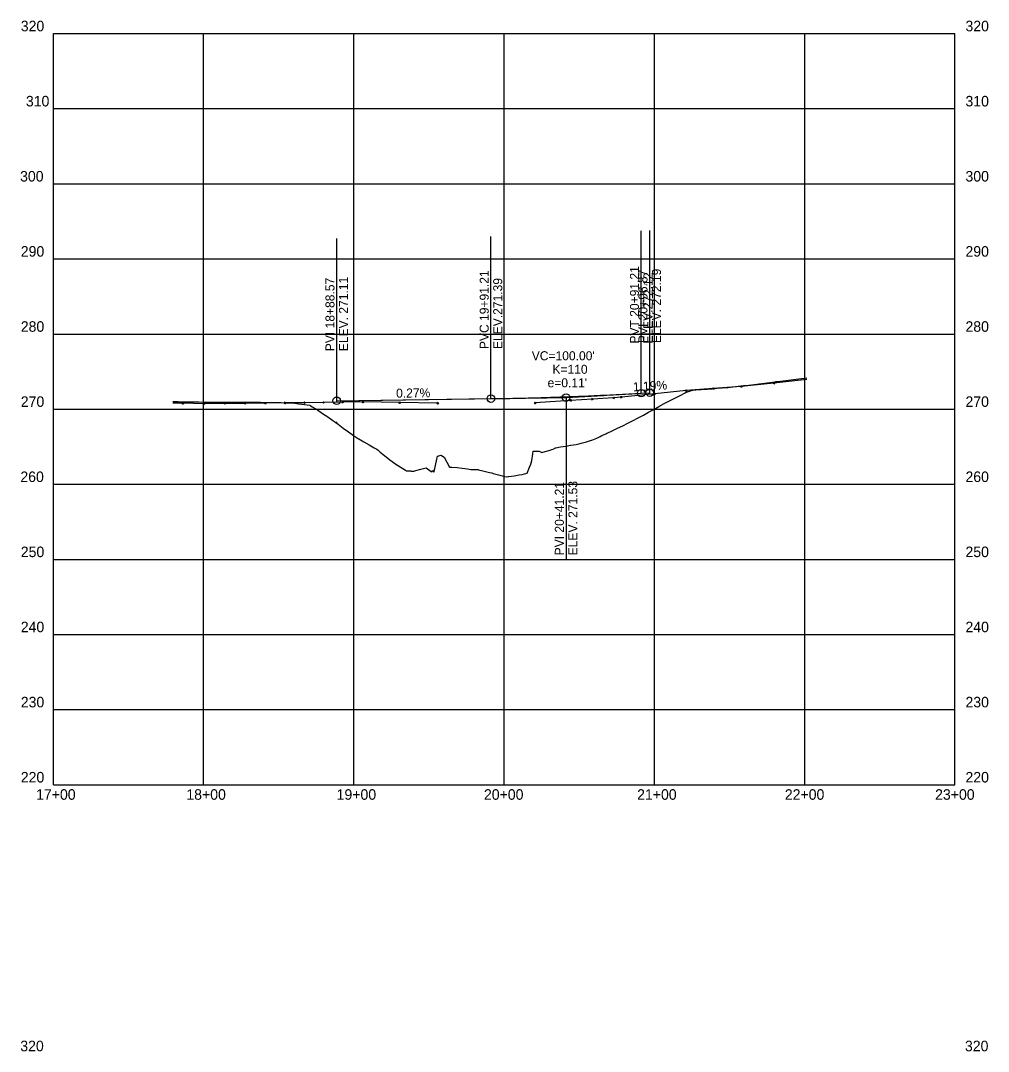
# Model space of a CAD drawing. Extents: x 1661035 to 1663788, y 668049 to 670894.
# Drawn here: x 1663144 to 1663788, y 670208 to 670894 of the extents above; entities that cross this region are included whole.
import ezdxf

# ---------------------------------------------------------------- set-up
doc = ezdxf.new("R2010")
doc.units = 0
for name, color, linetype in [('Default', 7, 'Continuous'), ('R_Axis', 7, 'Continuous'), ('R_Axis Annot', 7, 'Continuous'), ('R_Exist Surface', 7, 'Continuous'), ('R_Grid', 7, 'Continuous'), ('R_Point Sym', 7, 'Continuous'), ('R_Vert Alg', 7, 'Continuous'), ('R_Vert Alg Annot', 7, 'Continuous')]:
    doc.layers.add(name, color=color, linetype=linetype)

msp = doc.modelspace()

# ---------------------------------------------------------------- linework, layer by layer
at = {"layer": 'Default'}
for p, q in [((1663562.59, 670645.43), (1663562.59, 670646.43)), ((1663354.29, 670640.13), (1663354.29, 670641.13)), ((1663354.29, 670626.19), (1663354.29, 670627.19))]:
    msp.add_line(p, q, dxfattribs=at)
for points in [[(1663667.15, 670655.23), (1663645.28, 670652.95), (1663623.55, 670650.66), (1663604.92, 670649.27), (1663586.87, 670647.88), (1663565.94, 670645.75), (1663543.74, 670643.62), (1663538.59, 670643.09), (1663524.44, 670642.23), (1663509.96, 670641.37), (1663486.35, 670639.69)], [(1663421.48, 670639.45), (1663396.14, 670639.9), (1663371.72, 670640.36), (1663358.26, 670640.18), (1663345.5, 670640.01), (1663332.86, 670639.83), (1663319.87, 670639.66), (1663306.73, 670639.52), (1663293.35, 670639.39), (1663279.78, 670639.26), (1663266.06, 670639.13), (1663251.98, 670639.46), (1663245.29, 670639.62)]]:
    msp.add_lwpolyline(points, dxfattribs=at)
at = {"layer": 'R_Axis'}
for p, q in [((1663165.72, 670385.56), (1663165.72, 670885.56)), ((1663765.72, 670385.56), (1663765.72, 670885.56)), ((1663165.72, 670385.56), (1663765.72, 670385.56))]:
    msp.add_line(p, q, dxfattribs=at)
at = {"layer": 'R_Exist Surface'}
msp.add_lwpolyline([(1663245.29, 670640.65), (1663248.73, 670640.59), (1663252.16, 670640.53), (1663252.67, 670640.52), (1663252.8, 670640.52), (1663255.59, 670640.46), (1663259.03, 670640.39), (1663262.46, 670640.31), (1663265.89, 670640.23), (1663266.27, 670640.22), (1663267.32, 670640.22), (1663269.33, 670640.23), (1663272.76, 670640.25), (1663276.19, 670640.25), (1663279.29, 670640.26), (1663279.63, 670640.25), (1663282.07, 670640.25), (1663283.06, 670640.24), (1663286.49, 670640.24), (1663289.93, 670640.22), (1663292.43, 670640.21), (1663293.36, 670640.2), (1663296.8, 670640.17), (1663298.27, 670640.15), (1663300.23, 670640.14), (1663303.66, 670640.1), (1663305.78, 670640.08), (1663307.1, 670640.06), (1663310.37, 670640.02), (1663310.53, 670640.02), (1663313.96, 670639.96), (1663317.4, 670639.89), (1663319.44, 670639.84), (1663320.83, 670639.8), (1663320.98, 670639.79), (1663324.26, 670639.74), (1663325.07, 670639.73), (1663327.7, 670639.31), (1663328.91, 670639.11), (1663331.13, 670638.84), (1663334.56, 670638.42), (1663336.3, 670638.19), (1663336.98, 670637.8), (1663338, 670637.17), (1663339.83, 670636), (1663341.43, 670634.99), (1663344.86, 670632.74), (1663348.3, 670630.42), (1663351.73, 670628.01), (1663353.66, 670626.66), (1663355.18, 670625.53), (1663355.28, 670625.45), (1663358.62, 670622.95), (1663362.06, 670620.45), (1663365.51, 670618.03), (1663368.77, 670615.82), (1663368.95, 670615.71), (1663372.4, 670613.69), (1663375.84, 670611.74), (1663379.28, 670609.89), (1663380.97, 670609.02), (1663381.91, 670608.17), (1663382.73, 670607.46), (1663383.28, 670607.01), (1663386.17, 670604.6), (1663389.61, 670601.88), (1663391.09, 670600.79), (1663393.06, 670599.38), (1663396.5, 670597.08), (1663399.95, 670594.93), (1663400.6, 670594.54), (1663403.39, 670594.39), (1663403.83, 670594.36), (1663405.62, 670594.36), (1663406.83, 670594.69), (1663410.28, 670595.61), (1663413.72, 670596.54), (1663413.86, 670596.57), (1663417.17, 670594.08), (1663417.49, 670593.83), (1663418.3, 670594.71), (1663418.92, 670593.5), (1663419.47, 670596.05), (1663420.61, 670601.12), (1663421.34, 670604.28), (1663423.7, 670605.01), (1663424.05, 670604.77), (1663425.69, 670603.67), (1663427.5, 670600.34), (1663429.38, 670596.84), (1663430.08, 670596.96), (1663430.09, 670596.96), (1663430.94, 670596.91), (1663434.39, 670596.63), (1663437.83, 670596.26), (1663441.27, 670595.8), (1663443.51, 670595.45), (1663444.72, 670595.43), (1663448.16, 670595.36), (1663448.47, 670595.35), (1663448.67, 670595.26), (1663451.6, 670594.54), (1663455.05, 670593.69), (1663456.05, 670593.45), (1663457.46, 670593.11), (1663458.49, 670592.82), (1663461.94, 670591.85), (1663465.38, 670590.88), (1663467.09, 670590.4), (1663468.31, 670590.65), (1663468.82, 670590.72), (1663472.27, 670591.24), (1663475.71, 670591.77), (1663477.61, 670592.07), (1663479.16, 670592.44), (1663481.06, 670592.91), (1663482.6, 670596.85), (1663483.44, 670599.02), (1663484.05, 670601.29), (1663484.9, 670605.88), (1663485.11, 670607.49), (1663486.04, 670607.49), (1663487.43, 670607.48), (1663489.12, 670607.5), (1663489.49, 670607.33), (1663490.73, 670606.72), (1663492.93, 670607.34), (1663496.38, 670608.32), (1663497.49, 670608.63), (1663498.26, 670608.82), (1663499.82, 670609.76), (1663500, 670609.87), (1663503.26, 670610.39), (1663506.71, 670610.98), (1663509.79, 670611.54), (1663510.15, 670611.59), (1663513.6, 670612.13), (1663515.51, 670612.45), (1663516.34, 670612.67), (1663517.04, 670612.86), (1663520.48, 670613.81), (1663523.93, 670614.82), (1663524.17, 670614.89), (1663527.37, 670616.31), (1663529.67, 670617.37), (1663530.81, 670617.91), (1663533.3, 670619.13), (1663534.12, 670619.47), (1663534.26, 670619.54), (1663537.7, 670621.16), (1663539.88, 670622.22), (1663541.15, 670622.8), (1663544.59, 670624.44), (1663548.03, 670626.14), (1663551.48, 670627.9), (1663554.92, 670629.73), (1663558.37, 670631.61), (1663561.81, 670633.55), (1663562.27, 670633.82), (1663563.15, 670634.28), (1663565.25, 670635.4), (1663568.7, 670637.3), (1663572.21, 670639.24), (1663575.73, 670641.12), (1663579.25, 670642.95), (1663582.76, 670644.73), (1663586.23, 670646.42), (1663586.28, 670646.45), (1663586.4, 670646.51), (1663586.43, 670646.52), (1663586.44, 670646.53), (1663589.8, 670647.7), (1663591.36, 670648.23), (1663593.31, 670648.34), (1663596.83, 670648.55), (1663600.34, 670648.77), (1663601.05, 670648.81), (1663603.86, 670649.11), (1663606.1, 670649.35), (1663607.38, 670649.44), (1663610.89, 670649.71), (1663614.41, 670649.98), (1663614.9, 670650.02), (1663617.93, 670650.37), (1663621.44, 670650.78), (1663624.96, 670651.19), (1663625.68, 670651.27), (1663628.47, 670651.6), (1663630.43, 670651.82), (1663631.99, 670652.02), (1663635.51, 670652.47), (1663639.02, 670652.91), (1663642.54, 670653.35), (1663646.06, 670653.79), (1663646.58, 670653.85), (1663647.91, 670654.01), (1663649.57, 670654.21), (1663653.09, 670654.65), (1663656.61, 670655.08), (1663660.12, 670655.5), (1663663.64, 670655.93), (1663667.08, 670656.34), (1663667.15, 670656.34)], dxfattribs=at)
at = {"layer": 'R_Grid'}
for p, q in [((1663165.72, 670885.56), (1663765.72, 670885.56)), ((1663165.72, 670885.56), (1663765.72, 670885.56)), ((1663265.72, 670385.56), (1663265.72, 670885.56)), ((1663365.72, 670385.56), (1663365.72, 670885.56)), ((1663465.72, 670385.56), (1663465.72, 670885.56)), ((1663565.72, 670385.56), (1663565.72, 670885.56)), ((1663665.72, 670385.56), (1663665.72, 670885.56)), ((1663165.72, 670835.56), (1663765.72, 670835.56)), ((1663165.72, 670785.56), (1663765.72, 670785.56)), ((1663165.72, 670735.56), (1663765.72, 670735.56)), ((1663165.72, 670685.56), (1663765.72, 670685.56)), ((1663165.72, 670635.56), (1663765.72, 670635.56)), ((1663165.72, 670585.56), (1663765.72, 670585.56)), ((1663165.72, 670535.56), (1663765.72, 670535.56)), ((1663165.72, 670485.56), (1663765.72, 670485.56)), ((1663165.72, 670435.56), (1663765.72, 670435.56))]:
    msp.add_line(p, q, dxfattribs=at)
at = {"layer": 'R_Point Sym'}
for points in [[(1663645.28, 670652.95), (1663644.78, 670653.45), (1663645.28, 670652.95), (1663644.78, 670652.45), (1663645.28, 670652.95), (1663645.78, 670652.45), (1663645.28, 670652.95), (1663645.78, 670653.45)], [(1663565.94, 670645.75), (1663565.44, 670646.25), (1663565.94, 670645.75), (1663565.44, 670645.25), (1663565.94, 670645.75), (1663566.44, 670645.25), (1663565.94, 670645.75), (1663566.44, 670646.25)], [(1663586.87, 670647.88), (1663586.37, 670648.38), (1663586.87, 670647.88), (1663586.37, 670647.38), (1663586.87, 670647.88), (1663587.37, 670647.38), (1663586.87, 670647.88), (1663587.37, 670648.38)], [(1663604.92, 670649.27), (1663604.42, 670649.77), (1663604.92, 670649.27), (1663604.42, 670648.77), (1663604.92, 670649.27), (1663605.42, 670648.77), (1663604.92, 670649.27), (1663605.42, 670649.77)], [(1663623.55, 670650.66), (1663623.05, 670651.16), (1663623.55, 670650.66), (1663623.05, 670650.16), (1663623.55, 670650.66), (1663624.05, 670650.16), (1663623.55, 670650.66), (1663624.05, 670651.16)], [(1663251.98, 670639.46), (1663251.48, 670639.96), (1663251.98, 670639.46), (1663251.48, 670638.96), (1663251.98, 670639.46), (1663252.48, 670638.96), (1663251.98, 670639.46), (1663252.48, 670639.96)], [(1663266.06, 670639.13), (1663265.56, 670639.63), (1663266.06, 670639.13), (1663265.56, 670638.63), (1663266.06, 670639.13), (1663266.56, 670638.63), (1663266.06, 670639.13), (1663266.56, 670639.63)], [(1663279.78, 670639.26), (1663279.28, 670639.76), (1663279.78, 670639.26), (1663279.28, 670638.76), (1663279.78, 670639.26), (1663280.28, 670638.76), (1663279.78, 670639.26), (1663280.28, 670639.76)], [(1663293.35, 670639.39), (1663292.85, 670639.89), (1663293.35, 670639.39), (1663292.85, 670638.89), (1663293.35, 670639.39), (1663293.85, 670638.89), (1663293.35, 670639.39), (1663293.85, 670639.89)], [(1663306.73, 670639.52), (1663306.23, 670640.02), (1663306.73, 670639.52), (1663306.23, 670639.02), (1663306.73, 670639.52), (1663307.23, 670639.02), (1663306.73, 670639.52), (1663307.23, 670640.02)], [(1663319.87, 670639.66), (1663319.37, 670640.16), (1663319.87, 670639.66), (1663319.37, 670639.16), (1663319.87, 670639.66), (1663320.37, 670639.16), (1663319.87, 670639.66), (1663320.37, 670640.16)], [(1663332.86, 670639.83), (1663332.36, 670640.33), (1663332.86, 670639.83), (1663332.36, 670639.33), (1663332.86, 670639.83), (1663333.36, 670639.33), (1663332.86, 670639.83), (1663333.36, 670640.33)], [(1663345.5, 670640.01), (1663345, 670640.51), (1663345.5, 670640.01), (1663345, 670639.51), (1663345.5, 670640.01), (1663346, 670639.51), (1663345.5, 670640.01), (1663346, 670640.51)], [(1663358.26, 670640.18), (1663357.76, 670640.68), (1663358.26, 670640.18), (1663357.76, 670639.68), (1663358.26, 670640.18), (1663358.76, 670639.68), (1663358.26, 670640.18), (1663358.76, 670640.68)], [(1663371.72, 670640.36), (1663371.22, 670640.86), (1663371.72, 670640.36), (1663371.22, 670639.86), (1663371.72, 670640.36), (1663372.22, 670639.86), (1663371.72, 670640.36), (1663372.22, 670640.86)], [(1663396.14, 670639.9), (1663395.64, 670640.4), (1663396.14, 670639.9), (1663395.64, 670639.4), (1663396.14, 670639.9), (1663396.64, 670639.4), (1663396.14, 670639.9), (1663396.64, 670640.4)], [(1663421.48, 670639.45), (1663420.98, 670639.95), (1663421.48, 670639.45), (1663420.98, 670638.95), (1663421.48, 670639.45), (1663421.98, 670638.95), (1663421.48, 670639.45), (1663421.98, 670639.95)], [(1663486.35, 670639.69), (1663485.85, 670640.19), (1663486.35, 670639.69), (1663485.85, 670639.19), (1663486.35, 670639.69), (1663486.85, 670639.19), (1663486.35, 670639.69), (1663486.85, 670640.19)], [(1663509.96, 670641.37), (1663509.46, 670641.87), (1663509.96, 670641.37), (1663509.46, 670640.87), (1663509.96, 670641.37), (1663510.46, 670640.87), (1663509.96, 670641.37), (1663510.46, 670641.87)], [(1663524.44, 670642.23), (1663523.94, 670642.73), (1663524.44, 670642.23), (1663523.94, 670641.73), (1663524.44, 670642.23), (1663524.94, 670641.73), (1663524.44, 670642.23), (1663524.94, 670642.73)], [(1663538.59, 670643.09), (1663538.09, 670643.59), (1663538.59, 670643.09), (1663538.09, 670642.59), (1663538.59, 670643.09), (1663539.09, 670642.59), (1663538.59, 670643.09), (1663539.09, 670643.59)], [(1663543.74, 670643.62), (1663543.24, 670644.12), (1663543.74, 670643.62), (1663543.24, 670643.12), (1663543.74, 670643.62), (1663544.24, 670643.12), (1663543.74, 670643.62), (1663544.24, 670644.12)]]:
    msp.add_lwpolyline(points, dxfattribs=at)
at = {"layer": 'R_Vert Alg'}
for p, q in [((1663556.94, 670646.19), (1663562.59, 670646.52)), ((1663354.29, 670641.13), (1663456.94, 670642.54)), ((1663481.94, 670642.88), (1663506.94, 670643.22)), ((1663506.94, 670643.22), (1663531.94, 670644.7))]:
    msp.add_line(p, q, dxfattribs=at)
msp.add_lwpolyline([(1663456.94, 670642.54), (1663459.02, 670642.56), (1663461.1, 670642.6), (1663463.19, 670642.63), (1663465.27, 670642.67), (1663467.35, 670642.7), (1663469.44, 670642.74), (1663471.52, 670642.78), (1663473.6, 670642.83), (1663475.69, 670642.87), (1663477.77, 670642.92), (1663479.85, 670642.97), (1663481.94, 670643.02), (1663484.02, 670643.07), (1663486.1, 670643.13), (1663488.19, 670643.19), (1663490.27, 670643.25), (1663492.35, 670643.31), (1663494.44, 670643.37), (1663496.52, 670643.44), (1663498.6, 670643.5), (1663500.69, 670643.57), (1663502.77, 670643.64), (1663504.85, 670643.72), (1663509.02, 670643.87), (1663511.1, 670643.95), (1663513.19, 670644.03), (1663515.27, 670644.11), (1663517.35, 670644.2), (1663519.44, 670644.28), (1663521.52, 670644.37), (1663523.6, 670644.46), (1663525.69, 670644.56), (1663527.77, 670644.65), (1663529.85, 670644.75), (1663531.94, 670644.85), (1663534.02, 670644.95), (1663536.1, 670645.05), (1663538.19, 670645.15), (1663540.27, 670645.26), (1663542.35, 670645.37), (1663544.44, 670645.48), (1663546.52, 670645.59), (1663548.6, 670645.71), (1663550.69, 670645.82), (1663552.77, 670645.94), (1663554.85, 670646.06), (1663556.94, 670646.19)], dxfattribs=at)
at = {"layer": 'R_Vert Alg Annot'}
for p, q in [((1663354.29, 670671.13), (1663354.29, 670749.13)), ((1663456.94, 670672.54), (1663456.94, 670750.54)), ((1663556.94, 670676.19), (1663556.94, 670754.19)), ((1663562.59, 670676.52), (1663562.59, 670754.52)), ((1663456.94, 670642.54), (1663456.94, 670672.54)), ((1663556.94, 670646.19), (1663556.94, 670676.19)), ((1663562.59, 670646.52), (1663562.59, 670676.52)), ((1663354.29, 670641.13), (1663354.29, 670671.13)), ((1663354.29, 670641.13), (1663506.94, 670643.22)), ((1663506.94, 670643.22), (1663506.94, 670613.22)), ((1663506.94, 670613.22), (1663506.94, 670535.22))]:
    msp.add_line(p, q, dxfattribs=at)
for centre in [(1663456.94, 670642.54), (1663506.94, 670643.22), (1663556.94, 670646.19), (1663562.59, 670646.52), (1663354.29, 670641.13)]:
    msp.add_circle(centre, 2.5, dxfattribs=at)

# ---------------------------------------------------------------- texts
at = {"layer": 'R_Axis Annot'}
for s, height, p in [('320', 7, (1663144.03, 670887.06)), ('320', 7, (1663144.03, 670887.06)), ('320', 7, (1663772.72, 670887.06)), ('320', 7, (1663772.72, 670887.06)), ('310', 7, (1663147.43, 670837.06)), ('310', 7, (1663772.72, 670837.06)), ('300', 7, (1663143.56, 670787.06)), ('300', 7, (1663772.72, 670787.06)), ('290', 7, (1663144.03, 670737.06)), ('290', 7, (1663772.72, 670737.06)), ('280', 7, (1663144.03, 670687.06)), ('280', 7, (1663772.72, 670687.06)), ('270', 7, (1663144.03, 670637.06)), ('270', 7, (1663772.72, 670637.06)), ('260', 7, (1663143.75, 670587.06)), ('260', 7, (1663772.72, 670587.06)), ('250', 7, (1663144.03, 670537.06)), ('250', 7, (1663772.72, 670537.06)), ('240', 7, (1663144.03, 670487.06)), ('240', 7, (1663772.72, 670487.06)), ('230', 7, (1663144.03, 670437.06)), ('230', 7, (1663772.72, 670437.06)), ('220', 7, (1663144.03, 670387.06)), ('220', 7, (1663772.72, 670387.06)), ('-', 0.0001, (1663165.72, 670385.56)), ('17+00', 7, (1663154.22, 670375.56)), ('18+00', 7, (1663254.22, 670375.56)), ('19+00', 7, (1663354.22, 670375.56)), ('20+00', 7, (1663452.28, 670375.56)), ('21+00', 7, (1663554.22, 670375.56)), ('22+00', 7, (1663652.52, 670375.56)), ('23+00', 7, (1663752.52, 670375.56)), ('320', 7, (1663143.69, 670208.17)), ('320', 7, (1663143.69, 670208.17)), ('320', 7, (1663772.38, 670208.17)), ('320', 7, (1663772.38, 670208.17))]:
    msp.add_text(s, height=height, dxfattribs=at).set_placement(p)
at = {"layer": 'R_Vert Alg Annot'}
for s, rotation, p in [('PVC 19+91.21', 90, (1663455.44, 670675.54)), ('PVT 20+91.21', 90, (1663555.44, 670679.19)), ('PVI 20+96.87', 90, (1663561.09, 670679.52)), ('ELEV. 272.19', 90, (1663570.09, 670679.52)), ('PVI 18+88.57', 90, (1663352.79, 670674.13)), ('ELEV. 271.11', 90, (1663361.79, 670674.13)), ('ELEV.271.39', 90, (1663464.44, 670675.54)), ('ELEV.272.12', 90, (1663564.44, 670679.19)), ('1.19%', 3.39292, (1663551.59, 670647.37)), ('0.27%', 0.78622, (1663393.85, 670643.17)), ('PVI 20+41.21', 90, (1663505.44, 670538.22)), ('ELEV. 271.53', 90, (1663514.44, 670538.22))]:
    msp.add_text(s, height=6, rotation=rotation, dxfattribs=at).set_placement(p)
for s, p in [("VC=100.00'", (1663484.07, 670668.09)), ('K=110', (1663497.84, 670659.09)), ("e=0.11'", (1663494.61, 670650.09))]:
    msp.add_text(s, height=6, dxfattribs=at).set_placement(p)

doc.saveas('drawing.dxf')
